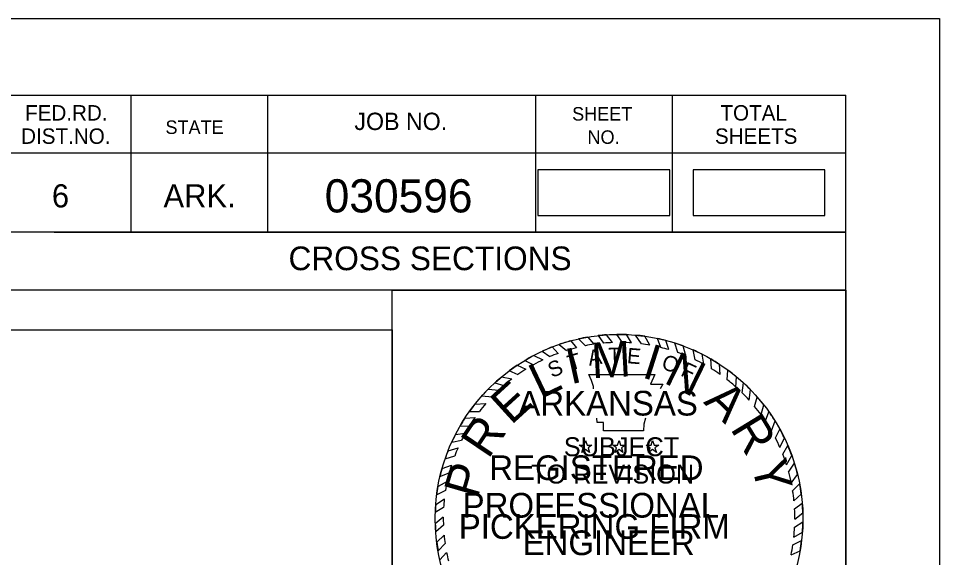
# Model space of a CAD drawing. Extents: x 1368910 to 1369601, y 380116 to 380950.
# Drawn here: x 1369553.81 to 1369600.52, y 380709.8 to 380737.11 of the extents above; entities that cross this region are included whole.
import ezdxf

# ---------------------------------------------------------------- set-up
doc = ezdxf.new("R2010")
doc.units = 0
for name, color, linetype in [('Notes', 7, 'Continuous'), ('R_Border', 7, 'Continuous'), ('R_Border Notes', 7, 'Continuous'), ('R_No Plot', 7, 'Continuous'), ('STAMP_PE_SEAL-INFO', 7, 'Continuous'), ('STAMP_PE_TXT', 7, 'Continuous'), ('STAMP_PRELIMINARY', 7, 'Continuous')]:
    doc.layers.add(name, color=color, linetype=linetype)

msp = doc.modelspace()

# ---------------------------------------------------------------- linework, layer by layer
at = {"layer": 'Notes'}
for points in [[(1369580.158, 380727.123), (1369586.842, 380727.123), (1369586.842, 380729.434), (1369580.158, 380729.434)], [(1369588.028, 380727.123), (1369594.712, 380727.123), (1369594.712, 380729.434), (1369588.028, 380729.434)]]:
    msp.add_lwpolyline(points, close=True, dxfattribs=at)
at = {"layer": 'R_Border'}
for p, q in [((1369279.59, 380733.219), (1369595.77, 380733.219)), ((1369559.51, 380733.219), (1369559.51, 380726.279)), ((1369566.45, 380733.219), (1369566.45, 380726.279)), ((1369580.03, 380733.219), (1369580.03, 380726.279)), ((1369586.97, 380733.219), (1369586.97, 380726.279)), ((1369595.77, 380527.759), (1369595.77, 380733.219)), ((1369595.77, 380730.279), (1369552.67, 380730.279)), ((1369595.77, 380730.299), (1369595.77, 380730.299)), ((1369595.77, 380726.279), (1369552.67, 380726.279)), ((1369555.63, 380726.279), (1369595.77, 380726.279)), ((1369595.77, 380723.339), (1369533.13, 380723.339))]:
    msp.add_line(p, q, dxfattribs=at)
at = {"layer": 'R_No Plot'}
for points in [[(1369267.182, 380737.113), (1369600.522, 380737.113), (1369600.522, 380523.776), (1369267.182, 380523.776)], [(1369593.77, 380632.489), (1369281.59, 380632.489), (1369281.59, 380731.219), (1369531.13, 380731.219), (1369531.13, 380721.339), (1369548.67, 380721.339), (1369572.77, 380721.339), (1369572.77, 380699.006), (1369593.77, 380699.006)], [(1369281.59, 380731.219), (1369531.13, 380731.219), (1369531.13, 380721.339), (1369548.67, 380721.339), (1369572.77, 380721.339), (1369572.77, 380699.006), (1369593.77, 380699.006), (1369593.77, 380529.759), (1369281.59, 380529.759)], [(1369572.77, 380723.339), (1369595.77, 380723.339), (1369595.77, 380699.006), (1369572.77, 380699.006)]]:
    msp.add_lwpolyline(points, close=True, dxfattribs=at)
at = {"layer": 'STAMP_PE_SEAL-INFO'}
for p, q in [((1369582.208, 380720.873), (1369582.564, 380720.53)), ((1369582.691, 380720.969), (1369582.99, 380720.602)), ((1369583.206, 380721.043), (1369583.487, 380720.66)), ((1369583.942, 380720.689), (1369583.63, 380721.082)), ((1369584.44, 380720.693), (1369584.161, 380721.103)), ((1369584.898, 380720.673), (1369584.639, 380721.097)), ((1369585.403, 380720.622), (1369585.111, 380721.066)), ((1369585.829, 380720.557), (1369585.572, 380721.013)), ((1369586.391, 380720.439), (1369586.217, 380720.898)), ((1369580.882, 380720.466), (1369581.176, 380720.141)), ((1369581.229, 380720.594), (1369581.61, 380720.289)), ((1369581.82, 380720.776), (1369582.108, 380720.429)), ((1369586.793, 380720.33), (1369586.634, 380720.799)), ((1369587.245, 380720.184), (1369587.103, 380720.663)), ((1369587.663, 380720.024), (1369587.519, 380720.52)), ((1369579.943, 380720.039), (1369580.406, 380719.814)), ((1369580.374, 380720.251), (1369580.763, 380719.976)), ((1369588.124, 380719.818), (1369588.022, 380720.316)), ((1369588.57, 380719.589), (1369588.483, 380720.098)), ((1369579.108, 380719.545), (1369579.55, 380719.342)), ((1369579.495, 380719.788), (1369579.927, 380719.565)), ((1369588.958, 380719.363), (1369588.918, 380719.863)), ((1369589.392, 380719.076), (1369589.361, 380719.591)), ((1369578.688, 380719.278), (1369579.143, 380719.073)), ((1369582.743, 380719.073), (1369586.087, 380719.073)), ((1369582.864, 380718.765), (1369582.743, 380719.073)), ((1369586.087, 380719.073), (1369585.862, 380718.581)), ((1369589.753, 380718.809), (1369589.787, 380719.296)), ((1369577.967, 380718.651), (1369578.426, 380718.512)), ((1369578.311, 380718.951), (1369578.84, 380718.85)), ((1369582.968, 380718.468), (1369582.864, 380718.765)), ((1369585.862, 380718.581), (1369586.495, 380718.581)), ((1369586.495, 380718.581), (1369586.35, 380718.353)), ((1369590.199, 380718.437), (1369590.219, 380718.959)), ((1369590.512, 380718.144), (1369590.581, 380718.643)), ((1369577.632, 380718.327), (1369578.176, 380718.286)), ((1369582.975, 380718.353), (1369582.968, 380718.468)), ((1369590.871, 380717.771), (1369590.938, 380718.297)), ((1369576.963, 380717.571), (1369577.512, 380717.594)), ((1369577.309, 380717.983), (1369577.831, 380717.944)), ((1369591.145, 380717.455), (1369591.281, 380717.926)), ((1369576.685, 380717.202), (1369577.19, 380717.197)), ((1369591.469, 380717.038), (1369591.604, 380717.537)), ((1369591.689, 380716.722), (1369591.866, 380717.186)), ((1369576.451, 380716.858), (1369576.967, 380716.891)), ((1369583.167, 380716.644), (1369583.14, 380716.862)), ((1369583.481, 380716.644), (1369583.167, 380716.644)), ((1369583.481, 380716.214), (1369583.481, 380716.644)), ((1369585.604, 380716.862), (1369585.526, 380716.552)), ((1369591.997, 380716.225), (1369592.179, 380716.716)), ((1369576.205, 380716.457), (1369576.694, 380716.477)), ((1369585.511, 380716.214), (1369583.481, 380716.214)), ((1369585.526, 380716.552), (1369585.511, 380716.214)), ((1369592.196, 380715.859), (1369592.423, 380716.303)), ((1369575.785, 380715.645), (1369576.288, 380715.748)), ((1369575.973, 380716.033), (1369576.472, 380716.098)), ((1369592.427, 380715.375), (1369592.653, 380715.859)), ((1369575.601, 380715.212), (1369576.106, 380715.358)), ((1369592.568, 380715.037), (1369592.831, 380715.471)), ((1369575.451, 380714.806), (1369575.936, 380714.942)), ((1369592.762, 380714.488), (1369593.033, 380714.963)), ((1369575.295, 380714.303), (1369575.772, 380714.472)), ((1369592.87, 380714.124), (1369593.164, 380714.576)), ((1369575.19, 380713.895), (1369575.66, 380714.088)), ((1369593.003, 380713.565), (1369593.322, 380714.012)), ((1369575.554, 380713.649), (1369575.089, 380713.4)), ((1369593.072, 380713.185), (1369593.426, 380713.538)), ((1369575.469, 380713.19), (1369575.023, 380712.968)), ((1369593.138, 380712.676), (1369593.511, 380713.012)), ((1369575.41, 380712.755), (1369574.973, 380712.474)), ((1369593.171, 380712.258), (1369593.561, 380712.55)), ((1369575.373, 380712.33), (1369574.952, 380712.073)), ((1369593.183, 380711.74), (1369593.588, 380712.061)), ((1369575.357, 380711.836), (1369574.952, 380711.501)), ((1369593.172, 380711.335), (1369593.591, 380711.612)), ((1369575.363, 380711.429), (1369574.972, 380711.105)), ((1369593.132, 380710.828), (1369593.567, 380711.085)), ((1369575.397, 380710.934), (1369575.025, 380710.577)), ((1369593.082, 380710.44), (1369593.525, 380710.659)), ((1369575.448, 380710.505), (1369575.094, 380710.132)), ((1369592.991, 380709.94), (1369593.446, 380710.135)), ((1369575.527, 380710.046), (1369575.188, 380709.678))]:
    msp.add_line(p, q, dxfattribs=at)
for radius, start, end in [(9.323, 99.7525, 102.7765), (9.323, 93.9381, 96.5517), (9.323, 87.7298, 90.6707), (9.323, 81.9732, 84.8236), (9.323, 75.3125, 77.9426), (9.323, 111.3124, 114.7026), (9.323, 105.2339, 109.0352), (8.914, 104.0352, 107.3615), (8.914, 98.258, 101.0329), (8.914, 92.1102, 95.0367), (8.914, 85.9628, 88.9097), (8.914, 79.9264, 82.696), (8.914, 73.5575, 76.2314), (9.323, 69.6061, 72.3058), (9.323, 117.6544, 120.8099), (8.914, 110.3086, 113.1659), (8.914, 67.6248, 70.504), (9.323, 63.1329, 66.2704), (9.323, 123.6199, 126.5906), (8.914, 115.6869, 119.1583), (8.914, 61.1558, 64.3784), (9.323, 56.9003, 60.0942), (8.914, 121.9746, 125.11), (8.914, 54.9238, 58.2702), (9.323, 50.3492, 53.7159), (9.323, 129.7326, 132.5376), (8.914, 127.5297, 130.9683), (8.914, 48.3016, 52.0395), (9.323, 44.3405, 47.3929), (9.323, 135.4021, 138.3031), (8.914, 133.1331, 136.2562), (8.914, 42.2212, 45.5512), (9.323, 141.6056, 144.4486), (8.914, 139.301, 142.5873), (9.323, 38.1247, 41.2316), (8.914, 36.135, 39.5311), (9.323, 31.9614, 35.4294), (9.323, 147.0072, 149.899), (8.914, 145.0197, 148.2104), (8.914, 29.9032, 33.6645), (9.323, 25.9391, 29.0125), (9.323, 152.864, 155.5189), (8.914, 151.0315, 153.573), (8.914, 23.7732, 27.2211), (8.914, 156.3402, 159.2319), (9.323, 19.9538, 23.3141), (9.323, 158.4077, 161.0701), (8.914, 17.6802, 21.4251), (9.323, 164.3068, 166.894), (8.914, 162.4331, 165.0013), (9.323, 13.8421, 17.4447), (8.914, 11.5444, 15.2364), (9.323, 170.0003, 172.6878), (8.914, 167.9048, 170.9039), (9.323, 7.5852, 10.8621), (8.914, 5.7599, 9.0606), (9.323, 175.7409, 178.2066), (8.914, 173.73, 176.4734), (9.323, 1.7215, 4.7268), (8.914, 359.7329, 3.0639), (9.323, 181.7251, 184.1626), (8.914, 179.6454, 182.2633), (9.323, 355.7156, 358.9569), (8.914, 353.8632, 357.1274), (9.323, 187.4204, 190.1927), (8.914, 185.4539, 188.234), (9.323, 349.8305, 353.0885), (8.914, 348.0778, 351.3435), (8.914, 191.2274, 193.9858)]:
    msp.add_arc((1369584.27, 380711.781), radius, start, end, dxfattribs=at)
at = {"layer": 'STAMP_PE_TXT'}
for p, q in [((1369582.496, 380715.497), (1369582.572, 380715.73)), ((1369582.572, 380715.73), (1369582.648, 380715.497)), ((1369584.194, 380715.497), (1369584.27, 380715.73)), ((1369584.27, 380715.73), (1369584.346, 380715.497)), ((1369585.892, 380715.497), (1369585.968, 380715.73)), ((1369585.968, 380715.73), (1369586.044, 380715.497)), ((1369582.449, 380715.353), (1369582.251, 380715.497)), ((1369582.251, 380715.497), (1369582.496, 380715.497)), ((1369582.374, 380715.12), (1369582.449, 380715.353)), ((1369582.572, 380715.264), (1369582.374, 380715.12)), ((1369582.77, 380715.12), (1369582.572, 380715.264)), ((1369582.648, 380715.497), (1369582.893, 380715.497)), ((1369582.893, 380715.497), (1369582.695, 380715.353)), ((1369582.695, 380715.353), (1369582.77, 380715.12)), ((1369584.147, 380715.353), (1369583.949, 380715.497)), ((1369583.949, 380715.497), (1369584.194, 380715.497)), ((1369584.072, 380715.12), (1369584.147, 380715.353)), ((1369584.27, 380715.264), (1369584.072, 380715.12)), ((1369584.468, 380715.12), (1369584.27, 380715.264)), ((1369584.346, 380715.497), (1369584.591, 380715.497)), ((1369584.591, 380715.497), (1369584.393, 380715.353)), ((1369584.393, 380715.353), (1369584.468, 380715.12)), ((1369585.845, 380715.353), (1369585.647, 380715.497)), ((1369585.647, 380715.497), (1369585.892, 380715.497)), ((1369585.77, 380715.12), (1369585.845, 380715.353)), ((1369585.968, 380715.264), (1369585.77, 380715.12)), ((1369586.166, 380715.12), (1369585.968, 380715.264)), ((1369586.044, 380715.497), (1369586.289, 380715.497)), ((1369586.289, 380715.497), (1369586.091, 380715.353)), ((1369586.091, 380715.353), (1369586.166, 380715.12))]:
    msp.add_line(p, q, dxfattribs=at)
at = {"layer": 'STAMP_PRELIMINARY'}
msp.add_circle((1369584.27, 380711.781), 9.323, dxfattribs=at)

# ---------------------------------------------------------------- texts
at = {"layer": 'R_Border'}
for s, height, p in [('FED.RD.', 0.7819, (1369554.15, 380731.939)), ('SHEET', 0.684, (1369581.89, 380731.939)), ('TOTAL', 0.7819, (1369589.41, 380731.939)), ('JOB NO.', 0.8792, (1369570.85, 380731.459)), ('STATE', 0.684, (1369561.27, 380731.259)), ('DIST.NO.', 0.7819, (1369553.95, 380730.759)), ('NO.', 0.684, (1369582.67, 380730.759)), ('SHEETS', 0.7819, (1369589.13, 380730.759)), ('6', 1.172, (1369555.51, 380727.539)), ('ARK.', 1.1723, (1369561.17, 380727.539))]:
    msp.add_text(s, height=height, dxfattribs=at).set_placement(p)
at = {"layer": 'R_Border Notes'}
for s, height, p in [('030596', 1.68, (1369569.343, 380727.284)), ('CROSS SECTIONS', 1.2, (1369567.509, 380724.357))]:
    msp.add_text(s, height=height, dxfattribs=at).set_placement(p)
at = {"layer": 'STAMP_PE_TXT'}
for s, rotation, p in [('T', 1.8248, (1369583.74, 380719.64)), ('E', 355.2002, (1369584.651, 380719.648)), ('T', 16.311, (1369581.792, 380719.257)), ('A', 9.0679, (1369582.754, 380719.51)), ('O', 342.2506, (1369586.377, 380719.371)), ('S', 23.5541, (1369580.869, 380718.885)), ('F', 335.0075, (1369587.343, 380719.033))]:
    msp.add_text(s, height=0.781, rotation=rotation, dxfattribs=at).set_placement(p)
for s, p in [('ARKANSAS', (1369579.162, 380716.992)), ('REGISTERED', (1369577.687, 380713.722)), ('PROFESSIONAL', (1369576.338, 380711.821)), ('ENGINEER', (1369579.379, 380709.919))]:
    msp.add_text(s, height=1.25, dxfattribs=at).set_placement(p)
at = {"layer": 'STAMP_PRELIMINARY'}
for s, rotation, p in [('I', 12.5248, (1369581.808, 380718.568)), ('M', 3.1074, (1369582.906, 380718.877)), ('I', 342.3164, (1369585.373, 380718.944)), ('N', 333.9382, (1369586.481, 380718.67)), ('L', 25.513, (1369580.279, 380717.809)), ('E', 42.3578, (1369578.796, 380716.478)), ('A', 315.6579, (1369588.515, 380717.645)), ('R', 301.3831, (1369589.883, 380716.331)), ('R', 56.2292, (1369577.641, 380714.745)), ('Y', 283.2593, (1369590.972, 380714.544)), ('P', 73.913, (1369577.091, 380712.722))]:
    msp.add_text(s, height=1.8, rotation=rotation, dxfattribs=at).set_placement(p)
for s, height, p in [('SUBJECT', 0.96, (1369581.47, 380714.931)), ('TO REVISION', 0.96, (1369579.805, 380713.546)), ('PICKERING FIRM', 1.25, (1369576.143, 380710.745))]:
    msp.add_text(s, height=height, dxfattribs=at).set_placement(p)

doc.saveas('drawing.dxf')
